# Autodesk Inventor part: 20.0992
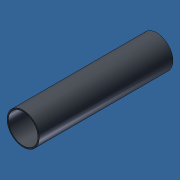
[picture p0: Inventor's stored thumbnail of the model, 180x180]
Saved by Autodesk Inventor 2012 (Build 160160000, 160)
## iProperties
Created: 2007-07
Part Number: 20.0992
Material: PVC-Piping
Document SubType Name: Modeling
Designer: Andy Moles
Density: 1.4 g/cm^3
Mass: 87.8239 g
Surface Area: 633.345 cm^2
Volume: 62.7313 cm^3
Description: CUT TO  L - 92mm(3.622")
Vendor: F
Stock Number: PVC TUBE 50X2
Author: Andy Moles
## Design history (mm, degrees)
sketch "Sketch1"
  geometry: C1 r 23 at (0, 0); C2 r 25 at (0, 0); 1 further point
  constraints: 2 centre point, 2 coincident
  dimensions: "d0" = 46 diameter of C1; "d1" = 50 diameter of C2
extrude "Extrusion1" new body sketch "Sketch1" stored distance "d2" = 208 (computed from BELT_WIDTH_L); taper "d3" = 0 deg
body "Solid1"
